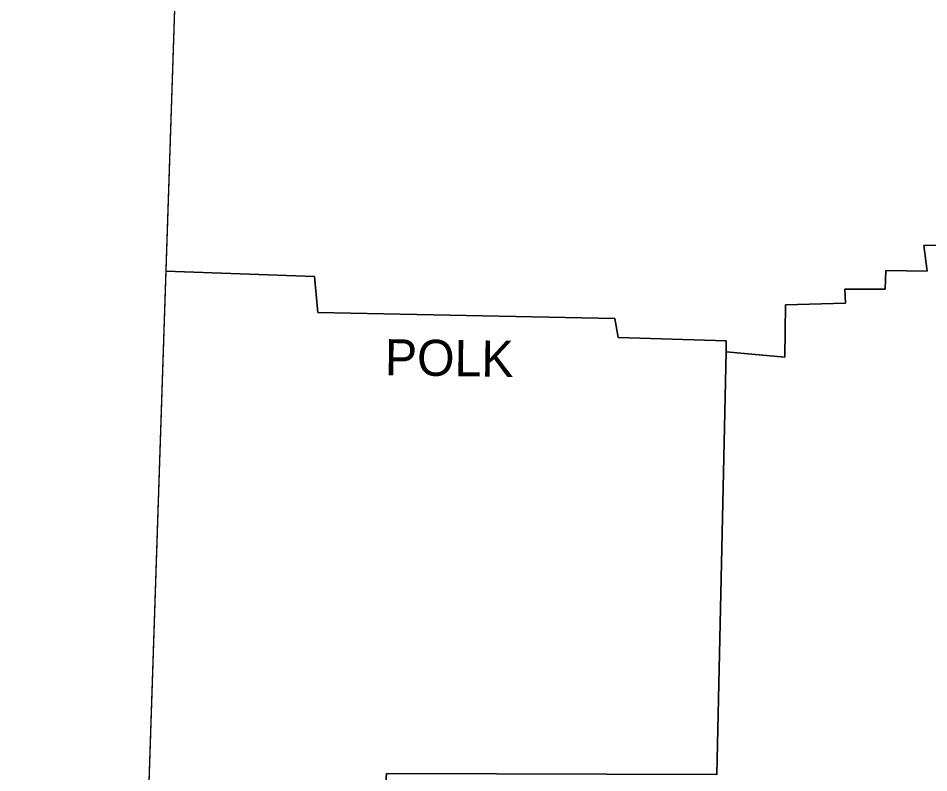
# Model space of a CAD drawing. Extents: x 1368042 to 1371376, y 380392 to 382637.
# Drawn here: x 1369113.2 to 1369334.7, y 381061.8 to 381245.3 of the extents above; entities that cross this region are included whole.
import ezdxf

# ---------------------------------------------------------------- set-up
doc = ezdxf.new("R2010")
doc.units = 0
doc.layers.add('Default', color=7, linetype='Continuous')
doc.layers.add('R_No Plot', color=7, linetype='Continuous')

msp = doc.modelspace()

# ---------------------------------------------------------------- linework, layer by layer
at = {"layer": 'Default'}
for points in [[(1369113.15, 381751.13), (1369156.38, 381404.07), (1369137.59, 380837.54)], [(1369344.2, 381275.78), (1369343.9, 381190.24), (1369333.46, 381190.03), (1369334.3, 381183.77), (1369324.27, 381183.97), (1369324.07, 381179.38), (1369314.25, 381179.38), (1369314.46, 381176.04), (1369299.84, 381175.62), (1369299.63, 381162.88), (1369285.43, 381164.14), (1369283.14, 381061.4), (1369202.74, 381061.61), (1369200.86, 381037.8), (1369203.78, 381035.71), (1369203.57, 381008.98), (1369143.36, 381011.63)], [(1369149.07, 381183.77), (1369185.2, 381182.51), (1369186.03, 381173.74), (1369258.29, 381172.28), (1369259.12, 381167.69), (1369285.43, 381166.85), (1369285.43, 381164.14)]]:
    msp.add_lwpolyline(points, dxfattribs=at)
at = {"layer": 'R_No Plot'}
for p, q in [((1369151.27, 381249.92), (1369149.07, 381183.77)), ((1369149.07, 381183.77), (1369143.36, 381011.63)), ((1369324.27, 381183.97), (1369324.07, 381179.38)), ((1369334.3, 381183.77), (1369324.27, 381183.97)), ((1369299.84, 381175.62), (1369299.63, 381162.88)), ((1369314.46, 381176.04), (1369299.84, 381175.62))]:
    msp.add_line(p, q, dxfattribs=at)
for points in [[(1369285.43, 381164.14), (1369299.63, 381162.88), (1369299.84, 381175.62), (1369314.46, 381176.04), (1369314.25, 381179.38), (1369324.07, 381179.38), (1369324.27, 381183.97), (1369334.3, 381183.77), (1369333.46, 381190.03), (1369343.9, 381190.24), (1369344.2, 381275.78)], [(1369343.9, 381190.24), (1369333.46, 381190.03), (1369334.3, 381183.77)], [(1369285.43, 381164.14), (1369285.43, 381166.85), (1369259.12, 381167.69), (1369258.29, 381172.28), (1369186.03, 381173.74), (1369185.2, 381182.51), (1369149.07, 381183.77)], [(1369149.07, 381183.77), (1369185.2, 381182.51), (1369186.03, 381173.74), (1369258.29, 381172.28), (1369259.12, 381167.69)], [(1369324.07, 381179.38), (1369314.25, 381179.38), (1369314.46, 381176.04)], [(1369259.12, 381167.69), (1369285.43, 381166.85), (1369285.43, 381164.14)], [(1369143.36, 381011.63), (1369203.57, 381008.98), (1369203.78, 381035.71), (1369200.86, 381037.8), (1369202.74, 381061.61), (1369283.14, 381061.4), (1369285.43, 381164.14)], [(1369299.63, 381162.88), (1369285.43, 381164.14), (1369283.14, 381061.4)]]:
    msp.add_lwpolyline(points, dxfattribs=at)

# ---------------------------------------------------------------- texts
at = {"layer": 'Default'}
msp.add_text('POLK', height=8.769, rotation=359.2152, dxfattribs=at).set_placement((1369202.32, 381158.5))

doc.saveas('drawing.dxf')
